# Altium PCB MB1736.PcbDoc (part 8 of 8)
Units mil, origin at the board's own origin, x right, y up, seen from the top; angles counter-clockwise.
Board outline 5905.51 x 3779.53 mil, 6 copper layers (Top Layer, L2_GND, L3_SIG, L4_VCC, L5_GND, Bottom Layer), stack 117.811 mil thick; 481 components, 387 nets, 1904 pads, 1200 vias.
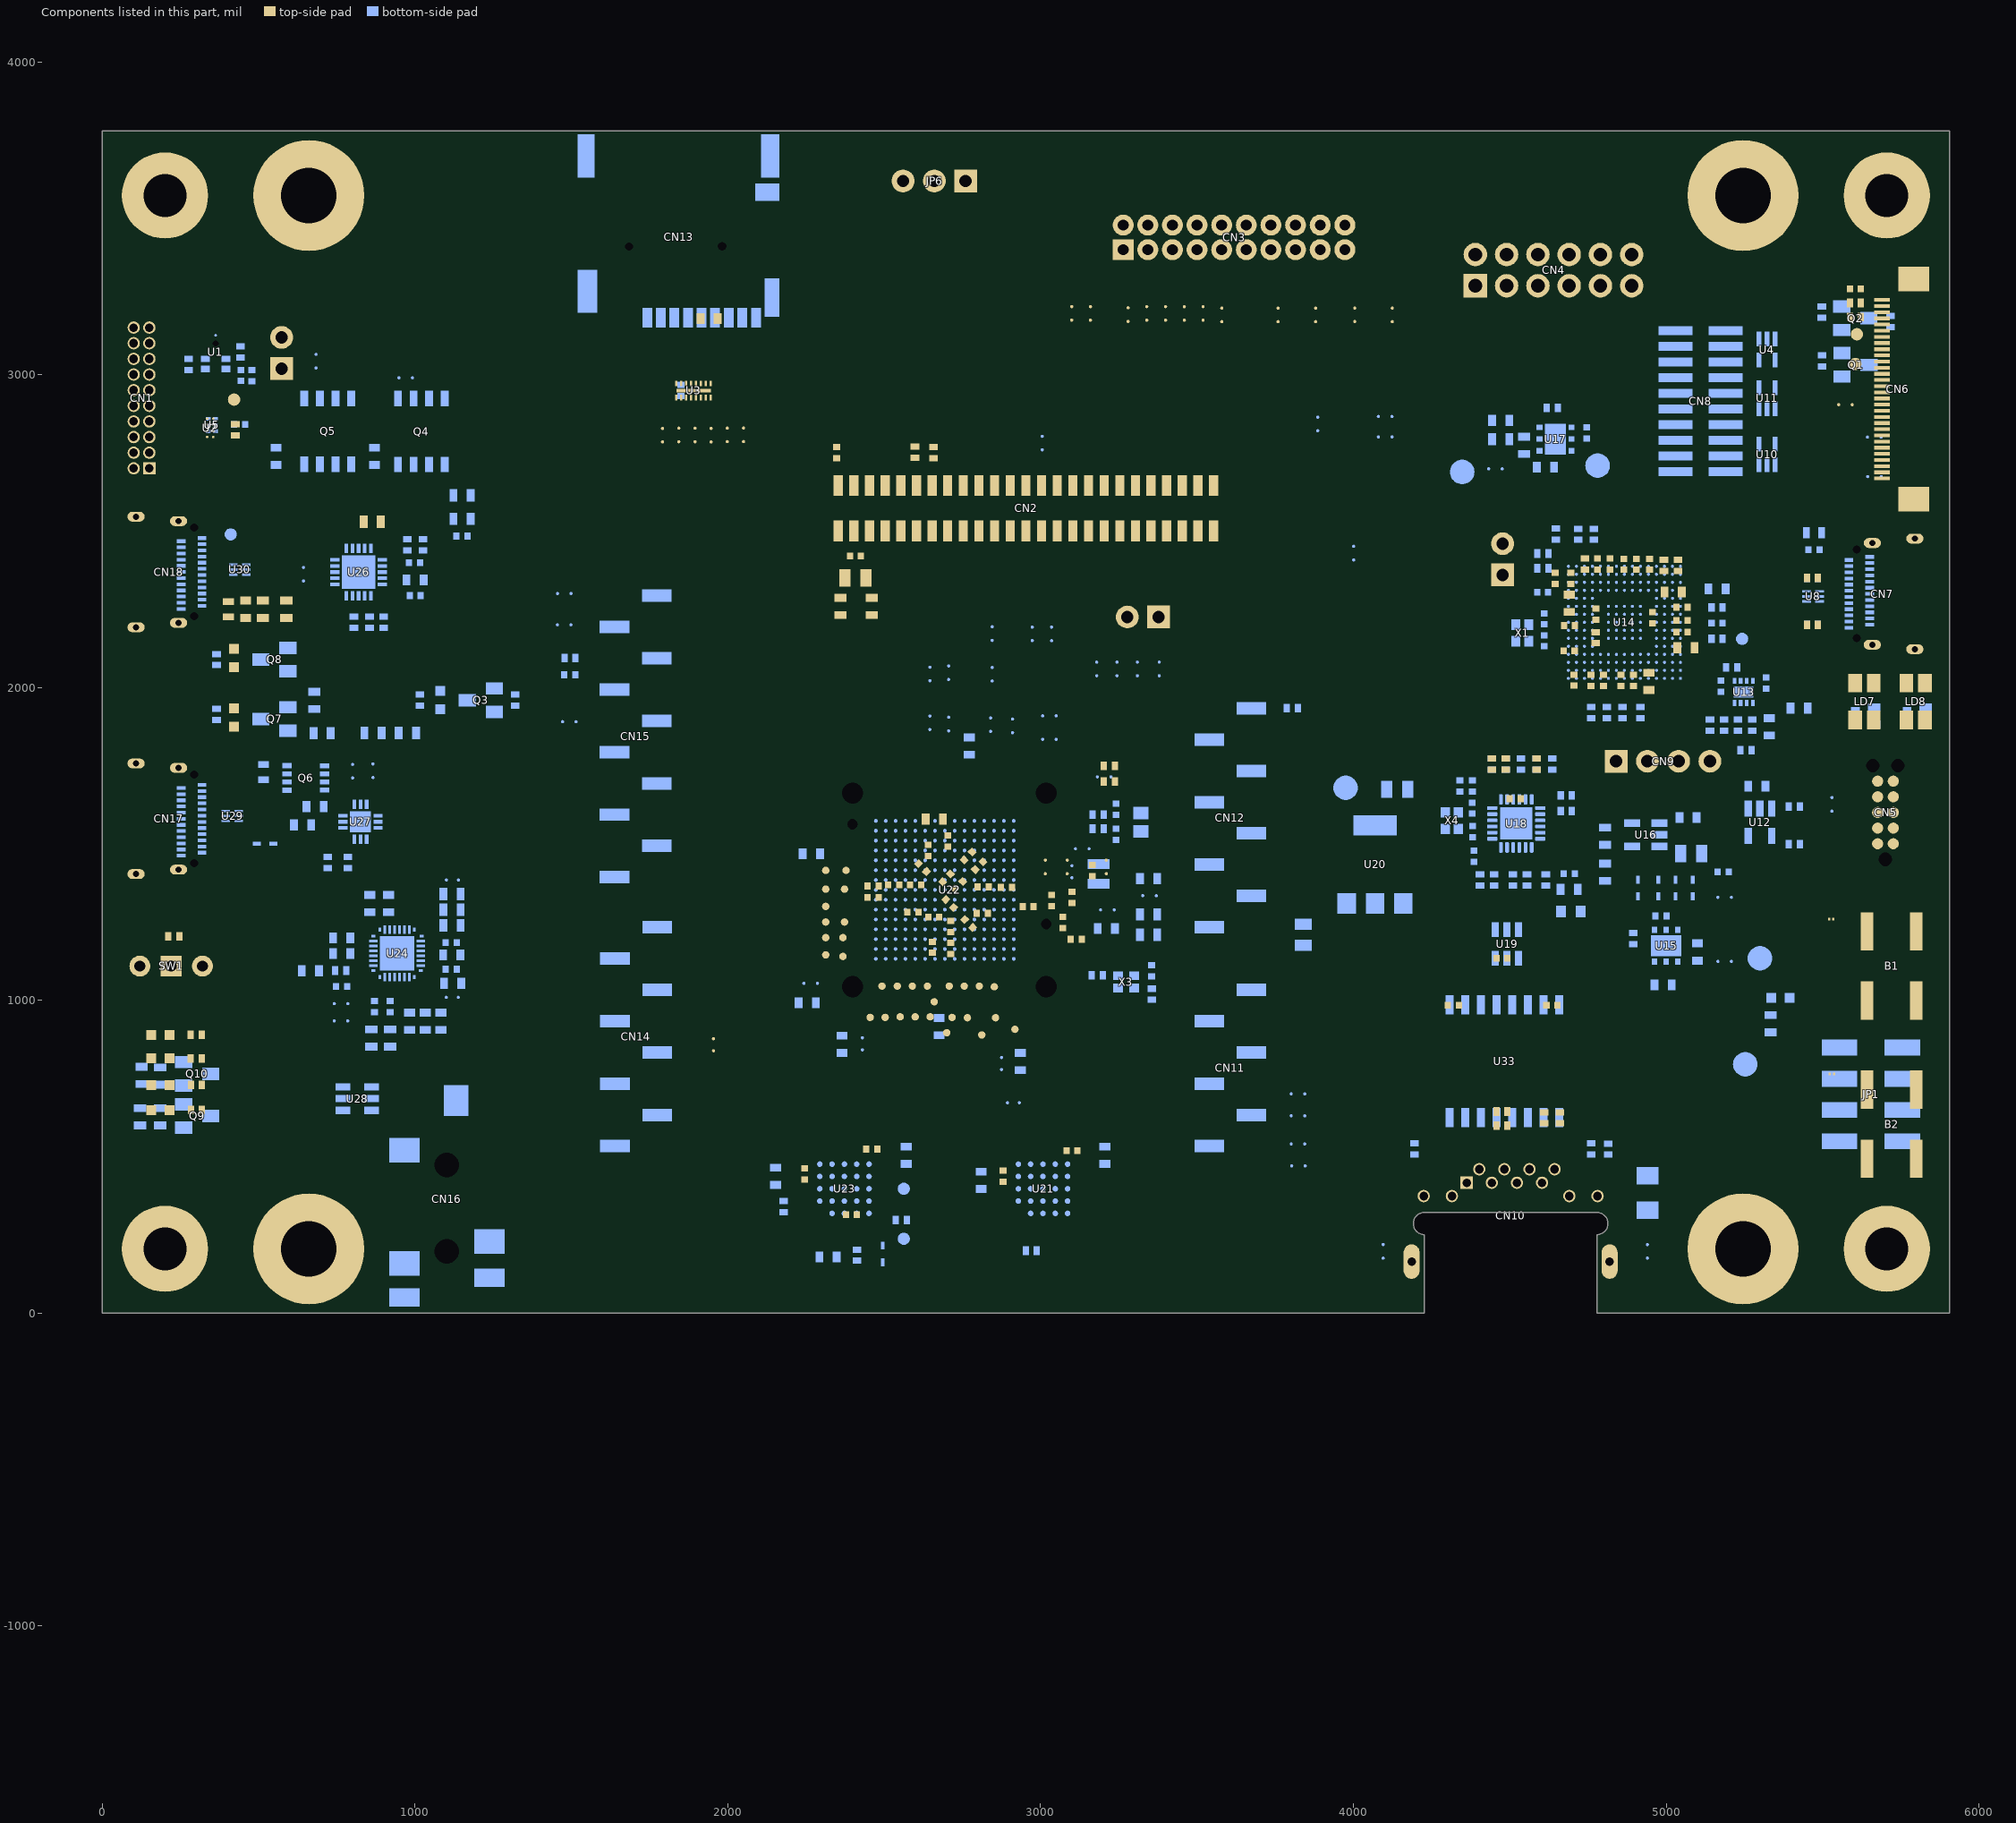
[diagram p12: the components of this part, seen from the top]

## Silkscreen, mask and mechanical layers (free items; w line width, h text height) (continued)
M20-Top Title Box:
  circle w10: c4301.22,-1459.57 r51.18
  region: 4282.53,-1174.67 3671.22,-1174.67 3643.89,-1244.57 3596.22,-1292.79 3541.22,-1219.57 3541.22,-1154.57 3586.22,-1099.57 3642.76,-1084.67 4282.53,-1084.67
  region: 3731.22,-1502.61 3307.76,-1502.61 3346.87,-1404.46 3656.22,-1404.46 3673.89,-1374.57 3760.84,-1474.9
  lines w10: 3346.87,-1404.46 3693,-1404.46 3572.29,-1265.18 cw(c3643.3,-1188.65) 3652.76,-1084.67 4312.76,-1084.67 4282.76,-1174.67 ; 3477.33,-1074.94 cw(c3572.84,-1113.15) 3582.16,-1010.7 ; 3478.87,-1073.66 3307.76,-1502.61 4068.49,-1502.61 ccw(c4078.28,-1394.95) 4178.64,-1435.1 ; 3547.36,-1228.58 3760.84,-1474.9 ; 3557.36,-1228.58 3766.22,-1469.57 ; 3557.36,-1218.58 3766.22,-1459.57 ; 3561.22,-1174.67 4072.76,-1174.67 ; 3562.36,-1213.58 3771.22,-1454.57 ; 3567.36,-1208.58 3776.22,-1449.57 ; 3572.36,-1203.58 3781.22,-1444.57 ; 3577.36,-1198.58 3786.22,-1439.57 ; 3579.52,-1121.71 3788.38,-1362.7 ; 3582.21,-1010.7 4347.94,-1010.7 4178.68,-1435 ; 3582.36,-1193.58 3789.08,-1432.09 ; 3582.36,-1183.58 3791.22,-1424.57 ; 3582.36,-1173.58 3791.22,-1414.57 ; 3582.36,-1138.58 3791.22,-1379.57 ; 3587.36,-1168.58 3796.22,-1409.57 ; 3587.36,-1153.58 3796.22,-1394.57 ; 3641.37,-1404.99 ccw(c3645.5,-1383.92) 3657.22,-1365.92 ; 3684.14,-1174.15 ccw(c3683.12,-1196.48) 3670.12,-1214.67 3763.22,-1322.1 cw(c3692.21,-1398.63) 3721.05,-1498.97 ; 3931.44,-1494.57 4045.19,-1164.67 ; 3940.19,-1492.61 4053.16,-1165.02 ; 3945.19,-1492.61 4058.16,-1165.02 ; 3955.19,-1492.61 4068.16,-1165.02 ; 3965.19,-1492.61 4078.16,-1165.02 ; 3975.19,-1492.61 4088.16,-1165.02 ; 3985.19,-1492.61 4098.16,-1165.02 ; 3995.19,-1492.61 4108.16,-1165.02 ; 4005.19,-1492.61 4118.16,-1165.02 ; 4015.19,-1492.61 4128.16,-1165.02 ; 4023.41,-1494.57 4137.16,-1164.67 ; 4137.16,-1174.67 4282.53,-1174.67 ; 4256.22,-1174.57 4286.22,-1084.57 ; 4262.76,-1174.67 4292.76,-1084.67 ; 4272.76,-1174.67 4302.76,-1084.67
  lines w11.81: 875.85,-1458.75 3238.06,-1458.75 ; 875.85,-1261.9 3238.06,-1261.9 ; 875.85,-1065.05 3238.06,-1065.05 ; 2450.66,-1655.6 2450.66,-1065.05 ; 3238.06,-1655.6 3238.06,-868.2 ; 3931.44,-1494.57 4023.41,-1494.57 ; 875.87,-1655.6 875.87,-868.2 4419.16,-868.2 4419.16,-1655.6 875.85,-1655.6
  text "Project: '.Board_Name'" at 915.23,-994.82 h118.11
  text "Layer:" at 915.24,-1194.98 h118.11
  text "Gerber:" at 2489.59,-1194.98 h118.11
  text "Variant: '.VariantName'" at 915.23,-1391.83 h118.11
  text "Ref: '.Board_Reference'" at 2494.59,-1391.83 h118.11
  text "R" at 4281.22,-1489.57 h60
  text "Date: '.Board_Document_Date'" at 915.23,-1588.68 h118.11
  text "Rev: '.Board_PCB_Revision'" at 2492.35,-1588.68 h118.11
M21-Bottom Title Box:
  circle w10: c1001.16,-1459.57 r51.18
  region: 1571.16,-1502.61 1994.63,-1502.61 1955.52,-1404.46 1646.16,-1404.46 1628.5,-1374.57 1541.54,-1474.9
  region: 1019.85,-1174.67 1631.16,-1174.67 1658.5,-1244.57 1706.16,-1292.79 1761.16,-1219.57 1761.16,-1154.57 1716.16,-1099.57 1659.63,-1084.67 1019.85,-1084.67
  lines w10: 999.63,-1084.67 1029.63,-1174.67 ; 1009.63,-1084.67 1039.63,-1174.67 ; 1016.16,-1084.57 1046.16,-1174.57 ; 1019.63,-1174.67 989.63,-1084.67 1649.63,-1084.67 cw(c1659.08,-1188.65) 1730.1,-1265.18 1609.38,-1404.46 1955.52,-1404.46 ; 1019.85,-1174.67 1165.22,-1174.67 ; 1123.7,-1435 954.44,-1010.7 1720.18,-1010.7 ; 1123.74,-1435.1 ccw(c1224.11,-1394.95) 1233.9,-1502.61 1994.63,-1502.61 1823.52,-1073.66 ; 1165.22,-1164.67 1278.98,-1494.57 ; 1174.23,-1165.02 1287.19,-1492.61 ; 1184.23,-1165.02 1297.19,-1492.61 ; 1194.23,-1165.02 1307.19,-1492.61 ; 1204.23,-1165.02 1317.19,-1492.61 ; 1214.23,-1165.02 1327.19,-1492.61 ; 1224.23,-1165.02 1337.19,-1492.61 ; 1229.63,-1174.67 1741.16,-1174.67 ; 1234.23,-1165.02 1347.19,-1492.61 ; 1244.23,-1165.02 1357.19,-1492.61 ; 1249.23,-1165.02 1362.19,-1492.61 ; 1257.19,-1164.67 1370.95,-1494.57 ; 1506.16,-1409.57 1715.02,-1168.58 ; 1506.16,-1394.57 1715.02,-1153.58 ; 1511.16,-1424.57 1720.02,-1183.58 ; 1511.16,-1414.57 1720.02,-1173.58 ; 1511.16,-1379.57 1720.02,-1138.58 ; 1513.31,-1432.09 1720.02,-1193.58 ; 1514.01,-1362.7 1722.87,-1121.71 ; 1516.16,-1439.57 1725.02,-1198.58 ; 1521.16,-1444.57 1730.02,-1203.58 ; 1526.16,-1449.57 1735.02,-1208.58 ; 1531.16,-1454.57 1740.02,-1213.58 ; 1536.16,-1469.57 1745.02,-1228.58 ; 1536.16,-1459.57 1745.02,-1218.58 ; 1541.54,-1474.9 1755.02,-1228.58 ; 1581.33,-1498.97 cw(c1610.18,-1398.63) 1539.16,-1322.1 1632.26,-1214.67 ccw(c1619.26,-1196.48) 1618.24,-1174.15 ; 1645.16,-1365.92 ccw(c1656.88,-1383.92) 1661.02,-1404.99 ; 1720.23,-1010.7 cw(c1729.54,-1113.15) 1825.06,-1074.94
  lines w11.81: 1278.98,-1494.57 1370.95,-1494.57 ; 2056.96,-1655.6 2056.96,-868.2 ; 2056.96,-1458.75 4419.16,-1458.75 ; 2056.96,-1261.9 4419.16,-1261.9 ; 2056.96,-1065.05 4419.16,-1065.05 ; 2844.36,-1655.6 2844.36,-1065.05 ; 875.85,-1655.6 4419.16,-1655.6 4419.16,-868.2 875.85,-868.2 875.85,-1655.6
  text "Project: '.Board_Name'" at 4372.15,-994.82 h118.11
  text "Gerber:" at 2797.79,-1194.98 h118.11
  text "Layer:" at 4372.14,-1194.98 h118.11
  text "Ref: '.Board_Reference'" at 2797.79,-1391.83 h118.11
  text "Variant: '.VariantName'" at 4372.15,-1391.83 h118.11
  text "R" at 1021.16,-1489.57 h60
  text "Rev: '.Board_PCB_Revision'" at 2800.04,-1588.68 h118.11
  text "Date: '.Board_Document_Date'" at 4372.15,-1588.68 h118.11

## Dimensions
0,3779.53 to 0,0 on Drill Drawing
5905.51,3779.53 to 0,3779.53 on Drill Drawing
5245.79,3573.62 to 659.96,3573.62 on Drill Drawing
5705.51,3573.61 to 200,3573.62 on Drill Drawing
200,3573.62 to 200,205.9 on Drill Drawing
0,3779.53 to 200,3573.62 on Drill Drawing
200,3573.62 to 0,3779.53 on Drill Drawing
5905.51,3779.53 to 5705.51,3573.61 on Drill Drawing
